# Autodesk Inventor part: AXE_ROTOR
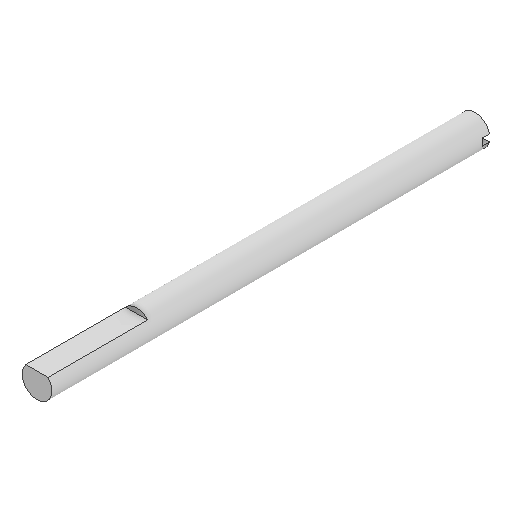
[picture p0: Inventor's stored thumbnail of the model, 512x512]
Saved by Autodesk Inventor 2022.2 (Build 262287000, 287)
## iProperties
Created: 2025-01
Part Number: AXE_ROTOR
Material: Generico
Document SubType Name: Modeling
Designer: 18907419
Density: 1 g/cm^3
Appearance: Default
Author: 18907419
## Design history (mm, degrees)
feature "AXE_ROTOR"
node "Solido1"
